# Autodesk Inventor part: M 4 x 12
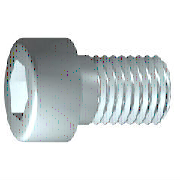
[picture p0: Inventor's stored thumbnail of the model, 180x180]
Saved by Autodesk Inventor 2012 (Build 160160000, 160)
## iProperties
IsCustomPart: 0
Created: 2009-02
Part Number: M 4 x 12
Material: 강, 연강
Description: 6각머리 태핑 나사
Document SubType Name: Modeling
Standard: KS B 1003
Designer: KYOUNG IL JANG
Standards Organization: KS
Language: ko-KR
Size Designation: M 4 x 12
Categories: <MemberInstance><Categories><Category DisplayName="조임쇠" InternalName="e4da775c-781d-43d5-af7c-5136215cf5a6" Mnemonic="FSTN"><Category DisplayName="볼트" InternalN
Density: 7.86 g/cm^3
Mass: 2.23465 g
Surface Area: 3.30853 cm^2
Volume: 0.284306 cm^3
Author: KYOUNG IL JANG
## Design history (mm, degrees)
workplane "Work Plane1"
fillet "Fillet2" dims "d30" = 0.1 (= R)
revolve "본체" stored, may be unused: angle "d10" = 90 deg
sketch "스케치2"
  geometry: L1 (0, -4.9)-(0, 4.9) reference; L2 (-4.9, 0)-(4.9, 0) reference; L3 (1.732, 0)-(0.866, -1.5); L4 (0.866, -1.5)-(-0.866, -1.5); L5 (-0.866, -1.5)-(-1.732, 0); L6 (-1.732, 0)-(-0.866, 1.5); L7 (-0.866, 1.5)-(0.866, 1.5); L8 (0.866, 1.5)-(1.732, 0); 2 further points
  constraints: 12 end point, 1 coincident, 1 horizontal alignment, 1 point on line, 12 other
extrude "슬롯" join sketch "스케치2" stored distance "d11" = 10; taper "d12" = 0 deg
body "Solid1"
fillet "모깎기1" dims "d17" = 0.4 (= RR)
feature "스레드" dims "d13" = 10.25 (= GEL), "d14" = 0
chamfer "모따기1" distance "d15" = 0.42941 (= -0.5 x SPD + 0.5 x GD); stored, may be unused: second distance "d16" = 0.42941 (= GUL), angle "d27" = 45 deg
sketch "스케치1"
  geometry: L1 (-1, 0)-(12, 0); L2 (12, 0)-(12, 2); L3 (12, 2)-(1.75, 2); L4 (1.75, 2)-(1.32, 2); L5 (1.32, 2)-(0, 2); L6 (0, 2)-(0, 3.5); L7 (0, 3.5)-(-4, 3.5); L8 (-4, 3.5)-(-4, 1.732); L9 (-4, 1.732)-(-2, 1.732); L10 (-2, 1.732)-(-1, 0); L11 (-7.2, 0)-(15.2, 0) reference; L12 (0, -0.7)-(0, 4.2) reference; L13 (1.75, 2)-(0, 2)
  constraints: 22 end point, 6 parallel, 2 collinear, 2 perpendicular, 1 horizontal, 1 point on line
  dimensions: "d1" = 10.25 distance from line of L3.end L2 (= GEL); "d2" = 0.42952 distance of L4.end L3.end (computed from GAL); "d3" = 4 distance between parallel lines of L8 L6 (= KOH); "d4" = 2 distance of L8.end L9.end (= INTI); "d5" = 60 deg angle of L10 L1; "d6" = 4 diameter of L3 L1 (= GD); "d7" = 4 diameter of L5 L1 (= BDM); "d8" = 3.4641 diameter of L9 L1 (= 1.1547 x SW); "d9" = 7 diameter of L7 L1 (= KOD); "d26" = 12 distance between parallel lines of L12 L2 (= NLG)
other parameters: "GD" = 4 (= NND) [user parameter; used in 2 equation terms], "NLG" = 12 [user parameter; used in 1 equation term], "GEL" = 10.25 [user parameter; used in 2 equation terms], "KOD" = 7 [user parameter; used in 1 equation term], "KOH" = 4 [user parameter; used in 1 equation term], "INTI" = 2 [user parameter; used in 1 equation term], "GAL" = 0.42941 (= 0.61345 x PTC) [user parameter; used in 1 equation term], "GUL" = 0.42941 (= 0.61345 x PTC) [user parameter; used in 1 equation term], "BDM" = 4 (= NND) [user parameter; used in 1 equation term], "SW" = 3 [user parameter; used in 2 equation terms], "RR" = 0.4 [user parameter; used in 1 equation term], "SPD" = 3.14117 (= NND - 1.2269 x PTC) [user parameter; used in 1 equation term], "d19" = 0, "d28" = 0, "d29" = 0, "R" = 0.1 [user parameter; used in 1 equation term], "PHH" = 0.2 [user parameter], "GD1" = 3.14117 (= THREADDIA - 1.2269 x PTC) [user parameter], "THREADDIA" = 4 [user parameter; used in 1 equation term], "FAWI" = 45 deg [user parameter], "TPU" = 14.28571 (computed from PTC) [user parameter], "PTC" = 0.7 [user parameter; used in 5 equation terms], "NND" = 4 [user parameter; used in 3 equation terms], "TOA" = 30 deg [user parameter], "E0" = 3.465 (= 1.155 x SW) [user parameter]
